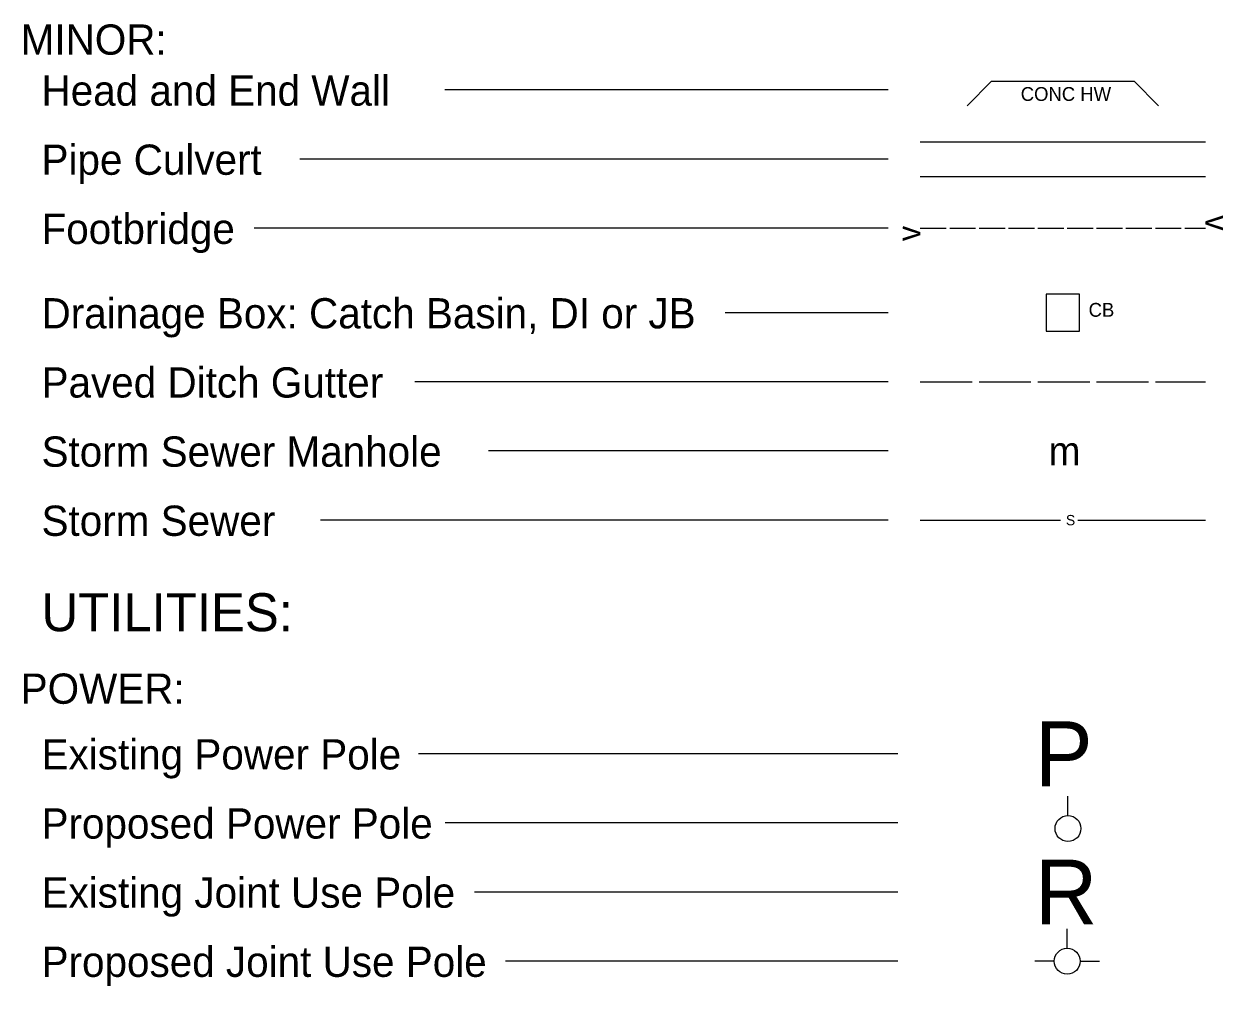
# Model space of a CAD drawing. Extents: x 1578579.3 to 1578613, y 915799 to 915821.
# Drawn here: x 1578597.89 to 1578604.83, y 915809.71 to 915815.28 of the extents above; entities that cross this region are included whole.
import ezdxf

# ---------------------------------------------------------------- set-up
doc = ezdxf.new("R2010")
doc.units = 0
doc.layers.add('Sheet Symbology CELL', color=7, linetype='Continuous')

msp = doc.modelspace()

# ---------------------------------------------------------------- linework, layer by layer
at = {"layer": 'Sheet Symbology CELL'}
for p, q in [((1578603.3468, 915814.804), (1578603.4883, 915814.9455)), ((1578603.4883, 915814.9455), (1578604.3133, 915814.9455)), ((1578604.3133, 915814.9455), (1578604.4548, 915814.804)), ((1578602.8898, 915814.8955), (1578600.3238, 915814.8955)), ((1578603.0758, 915814.5955), (1578604.7258, 915814.5955)), ((1578602.8898, 915814.4955), (1578599.4861, 915814.4955)), ((1578603.0758, 915814.3955), (1578604.7258, 915814.3955)), ((1578602.8898, 915814.0955), (1578599.2203, 915814.0955)), ((1578603.0758, 915814.0955), (1578603.2258, 915814.0955)), ((1578603.2458, 915814.0955), (1578603.3958, 915814.0955)), ((1578603.4158, 915814.0955), (1578603.5658, 915814.0955)), ((1578603.5858, 915814.0955), (1578603.7358, 915814.0955)), ((1578603.7558, 915814.0955), (1578603.9058, 915814.0955)), ((1578603.9258, 915814.0955), (1578604.0758, 915814.0955)), ((1578604.0958, 915814.0955), (1578604.2458, 915814.0955)), ((1578604.2658, 915814.0955), (1578604.4158, 915814.0955)), ((1578604.4358, 915814.0955), (1578604.5858, 915814.0955)), ((1578604.6058, 915814.0955), (1578604.7258, 915814.0955)), ((1578602.8898, 915813.6069), (1578601.9458, 915813.6069)), ((1578602.8898, 915813.2069), (1578600.1508, 915813.2069)), ((1578603.0758, 915813.2069), (1578603.3758, 915813.2069)), ((1578603.4158, 915813.2069), (1578603.7158, 915813.2069)), ((1578603.7558, 915813.2069), (1578604.0558, 915813.2069)), ((1578604.0958, 915813.2069), (1578604.3958, 915813.2069)), ((1578604.4358, 915813.2069), (1578604.7258, 915813.2069)), ((1578602.8898, 915812.8069), (1578600.5763, 915812.8069)), ((1578602.8898, 915812.4069), (1578599.6058, 915812.4069)), ((1578603.0758, 915812.4069), (1578603.8863, 915812.4069)), ((1578603.9863, 915812.4069), (1578604.7258, 915812.4069)), ((1578602.9456, 915811.0551), (1578600.1716, 915811.0551)), ((1578603.9301, 915810.6974), (1578603.9301, 915810.8099)), ((1578602.9456, 915810.6551), (1578600.3273, 915810.6551)), ((1578602.9456, 915810.2551), (1578600.4953, 915810.2551)), ((1578603.9258, 915809.9304), (1578603.9258, 915810.0429)), ((1578602.9456, 915809.8551), (1578600.6753, 915809.8551)), ((1578603.8508, 915809.8554), (1578603.7383, 915809.8554)), ((1578604.0008, 915809.8554), (1578604.1133, 915809.8554))]:
    msp.add_line(p, q, dxfattribs=at)
msp.add_lwpolyline([(1578603.8046, 915813.5006), (1578603.9968, 915813.5006), (1578603.9968, 915813.7134), (1578603.8046, 915813.7134)], close=True, dxfattribs=at)
for centre in [(1578603.9301, 915810.6224), (1578603.9258, 915809.8551)]:
    msp.add_circle(centre, 0.075, dxfattribs=at)

# ---------------------------------------------------------------- texts
for s, height, p in [('MINOR:', 0.175, (1578597.8701, 915815.0996)), ('Head and End Wall', 0.175001, (1578597.9906, 915814.8045)), ('Pipe Culvert', 0.175001, (1578597.9906, 915814.4047)), ('Footbridge', 0.175, (1578597.9908, 915814.0047)), ('Drainage Box: Catch Basin, DI or JB', 0.175001, (1578597.9908, 915813.5161)), ('Paved Ditch Gutter', 0.175001, (1578597.9908, 915813.1159)), ('Storm Sewer Manhole', 0.175001, (1578597.9908, 915812.7159)), ('m', 0.165, (1578603.8183, 915812.7244)), ('Storm Sewer', 0.175001, (1578597.9908, 915812.3159)), ('S', 0.06, (1578603.9183, 915812.3769)), ('UTILITIES:', 0.22, (1578597.9906, 915811.7641)), ('POWER:', 0.175, (1578597.8701, 915811.3444)), ('P', 0.375, (1578603.7383, 915810.8676)), ('Existing Power Pole', 0.175001, (1578597.9908, 915810.9644)), ('Proposed Power Pole', 0.175001, (1578597.9908, 915810.5644)), ('R', 0.375, (1578603.7383, 915810.0676)), ('Existing Joint Use Pole', 0.175001, (1578597.9908, 915810.1646)), ('Proposed Joint Use Pole', 0.175001, (1578597.9911, 915809.7644))]:
    msp.add_text(s, height=height, dxfattribs=at).set_placement(p)
for s, height, rotation, p in [('CONC HW', 0.08, 360, (1578603.6568, 915814.8322)), ('v', 0.132, 270.24085, (1578604.7256, 915814.1702)), ('v', 0.132, 89.75915, (1578603.0756, 915814.0207)), ('CB', 0.08, 360, (1578604.0496, 915813.5834))]:
    msp.add_text(s, height=height, rotation=rotation, dxfattribs=at).set_placement(p)

doc.saveas('drawing.dxf')
